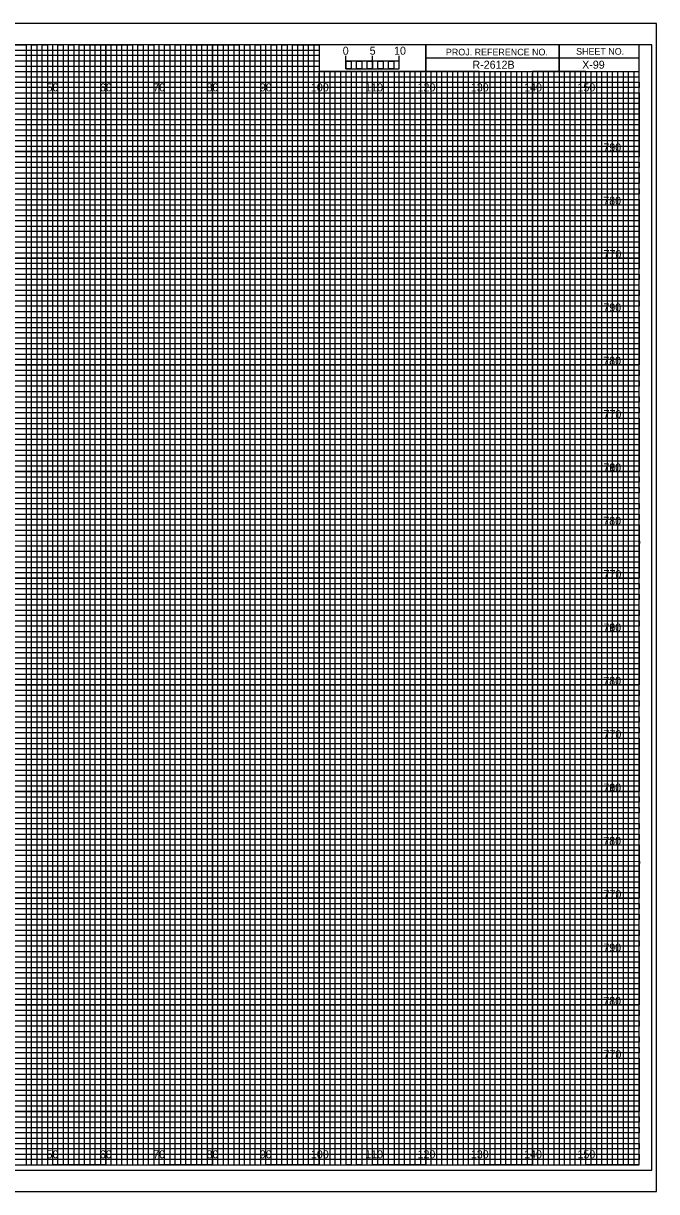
# Model space of a CAD drawing. Extents: x -13 to 323, y -5 to 214.
# Drawn here: x 204.5 to 323.3, y -5 to 214 of the extents above; entities that cross this region are included whole.
import ezdxf

# ---------------------------------------------------------------- set-up
doc = ezdxf.new("R2010")
doc.units = 0
for name, color, linetype in [('Prop XS Bar Scale Labels', 7, 'Continuous'), ('Prop XS Elevation Labels', 7, 'Continuous'), ('Prop XS Offset Labels', 7, 'Continuous'), ('Prop XS Project Number', 7, 'Continuous'), ('Prop XS Sheet Number', 7, 'Continuous'), ('Sheet Cross Section CELL', 7, 'Continuous'), ('Sheet Cross Section Grid Major CELL', 7, 'Continuous'), ('Sheet Cross Section Grid Middle CELL', 7, 'Continuous'), ('Sheet Cross Section Grid Minor 1 CELL', 7, 'Continuous'), ('Sheet Cross Section Grid Minor 2 CELL', 7, 'Continuous'), ('Sheet Cross Section Scale CELL', 7, 'Continuous'), ('Sheet Cutting Line CELL', 7, 'Continuous'), ('Sheet DOT Grid CELL', 7, 'Continuous'), ('Sheet Plot Border Inside CELL', 7, 'Continuous'), ('Sheet Plot Border Outside CELL', 7, 'Continuous')]:
    doc.layers.add(name, color=color, linetype=linetype)

msp = doc.modelspace()

# ---------------------------------------------------------------- linework, layer by layer
at = {"layer": 'Sheet Cross Section CELL'}
for p, q in [((305, 210), (305, 205)), ((305, 205), (305, 210)), ((280, 207.5), (280, 205)), ((320, 207.49), (280, 207.49)), ((280, 205), (320, 205))]:
    msp.add_line(p, q, dxfattribs=at)
for points in [[(320, 210), (0, 210), (0, 0), (320, 0)], [(280, 210), (260, 210), (260, 205.03), (280, 205.03)], [(320, 210), (280, 210), (280, 205), (320, 205)]]:
    msp.add_lwpolyline(points, close=True, dxfattribs=at)
at = {"layer": 'Sheet Cross Section Grid Major CELL'}
for p, q in [((210, 210), (200, 210)), ((210, 0), (210, 210)), ((230, 210), (220, 210)), ((220, 210), (220, 0)), ((230, 0), (230, 210)), ((250, 210), (240, 210)), ((240, 210), (240, 0)), ((250, 0), (250, 210)), ((260, 210), (260, 0)), ((270, 0), (270, 205)), ((290, 205), (280, 205)), ((280, 205), (280, 0)), ((290, 0), (290, 205)), ((310, 205), (300, 205)), ((300, 205), (300, 0)), ((310, 0), (310, 205)), ((220, 0), (210, 0)), ((240, 0), (230, 0)), ((260, 0), (250, 0)), ((280, 0), (270, 0)), ((300, 0), (290, 0)), ((320, 0), (310, 0)), ((320, 0), (320, 0))]:
    msp.add_line(p, q, dxfattribs=at)
for points in [[(0, 200), (320, 200), (320, 190), (0, 190)], [(0, 180), (320, 180), (320, 170), (0, 170)], [(0, 160), (320, 160), (320, 150), (0, 150)], [(0, 140), (320, 140), (320, 130), (0, 130)], [(0, 120), (320, 120), (320, 110), (0, 110)], [(0, 100), (320, 100), (320, 90), (0, 90)], [(0, 80), (320, 80), (320, 70), (0, 70)], [(0, 60), (320, 60), (320, 50), (0, 50)], [(0, 40), (320, 40), (320, 30), (0, 30)], [(0, 20), (320, 20), (320, 10), (0, 10)]]:
    msp.add_lwpolyline(points, dxfattribs=at)
at = {"layer": 'Sheet Cross Section Grid Middle CELL'}
for points in [[(195, 210), (205, 210), (205, 0), (215, 0), (215, 210), (225, 210), (225, 0), (235, 0), (235, 210), (245, 210), (245, 0), (255, 0), (255, 210), (259.93, 210), (260, 210), (260, 205), (264.99, 205), (264.99, 0), (275, 0), (275, 205), (285, 205), (285, 0), (295, 0), (295, 205), (305, 205), (305, 0), (315, 0), (315, 205)], [(0, 205), (275, 205)], [(0, 185), (320, 185), (320, 195), (0, 195)], [(0, 165), (320, 165), (320, 175), (0, 175)], [(0, 145), (320, 145), (320, 155), (0, 155)], [(0, 125), (320, 125), (320, 135), (0, 135)], [(0, 105), (320, 105), (320, 115), (0, 115)], [(0, 85), (320, 85), (320, 95), (0, 95)], [(0, 65), (320, 65), (320, 75), (0, 75)], [(0, 45), (320, 45), (320, 55), (0, 55)], [(0, 25), (320, 25), (320, 35), (0, 35)], [(0, 5), (320, 5), (320, 15), (0, 15)]]:
    msp.add_lwpolyline(points, dxfattribs=at)
at = {"layer": 'Sheet Cross Section Grid Minor 1 CELL'}
for p, q in [((0, 209), (260, 209)), ((260, 209), (260, 207.98)), ((260, 207.98), (0, 207.98)), ((0, 207), (260, 207)), ((260, 205.89), (0, 205.89)), ((260, 207), (260, 205.89)), ((0, 204), (320, 204))]:
    msp.add_line(p, q, dxfattribs=at)
for points in [[(0, 203), (270, 203), (320, 203), (320, 202), (0, 202)], [(0, 201), (320, 201), (320, 199), (0, 199)], [(0, 198), (320, 198), (320, 197), (0, 196.98)], [(0, 196), (320, 196), (320, 194), (0, 194)], [(0, 193), (320, 193), (320, 192), (0, 192)], [(0, 191), (320, 191), (320, 189), (0, 189)], [(0, 188), (320, 188), (320, 187), (0, 187)], [(0, 186), (320, 186), (320, 184), (0, 184)], [(0, 183), (320, 183), (320, 182), (0, 182)], [(0, 181), (320, 181), (320, 179), (0, 179)], [(0, 178), (320, 178), (320, 177), (0, 177)], [(0, 176), (320, 176), (320, 173.95), (320, 173), (320, 172), (0, 172)], [(0, 174), (320, 174), (320, 173), (0, 173)], [(0, 171), (320, 171), (320, 169), (0, 169.03)], [(0, 169.03), (320, 169), (320, 168), (0, 168)], [(0, 167), (320, 167), (320, 166), (0, 166)], [(0, 164), (320, 164), (320, 163), (0, 163)], [(0, 162), (320, 162), (320, 161), (0, 161)], [(-0.07, 158.89), (320, 158.89), (320, 157.88), (-0.07, 157.88)], [(0, 157), (320, 157), (320, 156), (0, 156)], [(0, 154), (320, 154), (320, 153), (0, 153)], [(0, 152), (320, 152), (320, 151), (0, 151)], [(0, 149), (320, 149), (320, 148), (0, 148)], [(0, 147), (320, 147), (320, 146), (0, 146)], [(0, 144), (320, 144), (320, 143), (0, 143)], [(0, 142), (320, 142), (320, 141), (0, 141)], [(0, 139), (320, 139), (319.99, 137.98), (0, 138)], [(0, 137), (320, 137), (320, 136), (0, 136)], [(0, 134), (320, 134), (320, 133), (0, 133)], [(0, 132), (320, 132), (320, 131), (0, 131)], [(0, 129), (320, 129), (320, 128), (0, 128)], [(0, 127), (320, 127), (320, 126), (0, 126)], [(0, 124), (320, 124), (320, 123), (0, 123)], [(0, 122), (320, 122), (320, 121), (0, 121)], [(0, 119), (320, 119), (320, 118), (0, 118)], [(0, 116.99), (320.07, 116.91), (320, 116), (0, 116)], [(0, 114), (320, 114), (320, 113), (0, 113)], [(0, 112), (320, 112), (320, 111), (0, 111)], [(0, 109), (320, 109), (320, 108), (0, 108)], [(0, 107), (320, 107), (320, 106), (0, 106)], [(0, 104), (320, 104), (320, 103), (0, 103)], [(0, 102), (320, 102), (320, 101), (0, 101)], [(0, 99), (320, 99), (320, 98), (0, 98)], [(0, 97), (320, 97), (320, 96), (0, 96)], [(0, 94), (320, 94), (320, 93), (0, 93)], [(0, 92), (320, 92), (320, 91), (0, 91)], [(0, 89), (320, 89), (320, 88), (0, 88)], [(0, 87), (320, 87), (320, 86), (0, 86)], [(0, 84), (320, 84), (320, 83), (0, 83)], [(0, 82), (320, 82), (320, 81), (0, 81)], [(0, 79), (320, 79), (319.99, 77.98), (0, 78)], [(0, 77), (320, 77), (320, 76), (0, 76)], [(0, 74), (320, 74), (320, 73), (0, 73)], [(0, 72), (320, 72), (320, 71), (0, 71)], [(0, 69), (320, 69), (320, 68), (0, 68)], [(0, 67), (320, 67), (320, 66), (0, 66)], [(0, 64), (320, 64), (320, 63), (0, 63)], [(0, 62), (320, 62), (320, 61), (0, 61)], [(0, 59), (320, 59), (320, 58), (0, 58)], [(0, 56.99), (320.07, 56.91), (320, 56), (0, 56)], [(0, 54), (320, 54), (320, 53), (0, 53)], [(0, 52), (320, 52), (320, 51), (0, 51)], [(0, 49), (320, 49), (320, 48), (0, 48)], [(0, 47), (320, 47), (320, 46), (0, 46)], [(0, 44), (320, 44), (320, 43), (0, 43)], [(0, 42), (320, 42), (320, 41), (0, 41)], [(0, 39), (320, 39), (320, 38), (0, 38)], [(0, 37), (320, 37), (320, 36), (0, 36)], [(0, 34), (320, 34), (320, 33), (0, 33)], [(0, 32), (320, 32), (320, 31), (0, 31)], [(0, 29), (320, 29), (320, 28), (0, 28)], [(0, 27), (320, 27), (320, 26), (0, 26)], [(0, 24), (320, 24), (320, 23), (0, 23)], [(0, 22), (320, 22), (320, 21), (0, 21)], [(0, 19), (320, 19), (320, 18), (0, 18)], [(0, 17), (320, 17), (320, 16), (0, 16)], [(0, 14), (320, 14), (320, 13), (0, 13)], [(0, 12), (320, 12), (320, 11), (0, 11)], [(0, 9), (320, 9), (320, 8), (0, 8)], [(0, 7), (320, 7), (320, 6), (0, 6)], [(0, 4), (320, 4), (320, 3), (0, 3)], [(0, 2), (320, 2), (320, 1), (0, 1)]]:
    msp.add_lwpolyline(points, dxfattribs=at)
at = {"layer": 'Sheet Cross Section Grid Minor 2 CELL'}
for p, q in [((267, 205), (266.01, 205)), ((266.01, 205), (266.01, 0)), ((267, 0), (267, 205)), ((269, 205), (268, 205)), ((268, 205), (268, 0)), ((269, 0), (269, 205)), ((266.01, 0), (265, 0)), ((268, 0), (267, 0))]:
    msp.add_line(p, q, dxfattribs=at)
for points in [[(205, 0), (206, 0), (206, 210), (207, 210), (207, 0)], [(207, 0), (208, 0), (208, 210), (209, 210), (209, 0)], [(210, 0), (211, 0), (211, 210), (212, 210), (212, 0)], [(212, 0), (213, 0), (213, 210), (214, 210), (214, 0)], [(215, 0), (216, 0), (216, 210), (217, 210), (217, 0)], [(217, 0), (218, 0), (218, 210), (219, 210), (219, 0)], [(220, 0), (221, 0), (221, 210), (222, 210), (222, 0)], [(222, 0), (223, 0), (223, 210), (224, 210), (224, 0)], [(225, 0), (226, 0), (226, 210), (227, 210), (227, 0)], [(227, 0), (228, 0), (228, 210), (229, 210), (229, 0)], [(230, 0), (231, 0), (231, 210), (232, 210), (232, 0)], [(232, 0), (233, 0), (233, 210), (234, 210), (234, 0)], [(235, 0), (236, 0), (236, 210), (237, 210), (237, 0)], [(237, 0), (238, 0), (238, 210), (239, 210), (239, 0)], [(240, 0), (241, 0), (241, 210), (242, 210), (242, 0)], [(242, 0), (243, 0), (243, 210), (244, 210), (244, 0)], [(245, 0), (246, 0), (246, 210), (247, 210), (247, 0)], [(247, 0), (248, 0), (248, 210), (249, 210), (249, 0)], [(250, 0), (251, 0), (251, 210), (252, 210), (252, 0)], [(252, 0), (253, 0), (253, 210), (254, 210), (254, 0)], [(255, 0), (256, 0), (256, 210), (257, 210), (257, 0)], [(257, 0), (258, 0), (258, 210), (259, 210), (259, 0)], [(260, 0), (261, 0), (261, 205), (262.02, 205), (262.02, 0)], [(262, 0), (263, 0), (263, 205), (263.99, 205), (263.99, 0)], [(270, 0), (270.98, 0), (270.98, 205), (272, 205), (272, 0)], [(272, 0), (273, 0), (273, 205), (274.05, 205), (274.05, 0)], [(275, 0), (276, 0), (276, 205), (277, 205), (277, 0)], [(277, 0), (278, 0), (278, 205), (279, 205), (279, 0)], [(280, 0), (281, 0), (281, 205), (282, 205), (282, 0)], [(282, 0), (283, 0), (283, 205), (284, 205), (284, 0)], [(285, 0), (286, 0), (286, 205), (287, 205), (287, 0)], [(287, 0), (288, 0), (288, 205), (289, 205), (289, 0)], [(290, 0), (291, 0), (291, 205), (292, 205), (292, 0)], [(292, 0), (293, 0), (293, 205), (294, 205), (294, 0)], [(295, 0), (296, 0), (296, 205), (297, 205), (297, 0)], [(297, 0), (298, 0), (298, 205), (299, 205), (299, 0)], [(300, 0), (301, 0), (301, 205), (302, 205), (302, 0)], [(302, 0), (303, 0), (303, 205), (304, 205), (304, 0)], [(305, 0), (306, 0), (306, 205), (307, 205), (307, 0)], [(307, 0), (308, 0), (308, 205), (309, 205), (309, 0)], [(310, 0), (311, 0), (311, 205), (312, 205), (312, 0)], [(312, 0), (313, 0), (313, 205), (314, 205), (314, 0)], [(315, 0), (316, 0), (316, 205), (317, 205), (317, 0)], [(317, 0), (318, 0), (318, 205), (319, 205), (319, 0)]]:
    msp.add_lwpolyline(points, dxfattribs=at)
at = {"layer": 'Sheet Cross Section Scale CELL'}
for p, q in [((265, 205.49), (265, 207.9)), ((265, 206.9), (265, 207.9)), ((270, 205.49), (270, 207.9)), ((275, 205.49), (275, 207.9)), ((275, 206.9), (275, 207.9))]:
    msp.add_line(p, q, dxfattribs=at)
for points in [[(275, 206.9), (265, 206.9), (265, 205.49), (275, 205.49)], [(265, 206.9), (266, 206.9), (266, 205.49), (265, 205.49)], [(267, 206.9), (268, 206.9), (268, 205.49), (267, 205.49)], [(269, 206.9), (270, 206.9), (270, 205.49), (269, 205.49)], [(271, 206.9), (272, 206.9), (272, 205.49), (271, 205.49)], [(273, 206.9), (274, 206.9), (274, 205.49), (273, 205.49)]]:
    msp.add_lwpolyline(points, close=True, dxfattribs=at)
at = {"layer": 'Sheet Cutting Line CELL'}
for p, q in [((323.3, 214), (-13.4, 214)), ((-13.4, -5), (323.3, -5))]:
    msp.add_line(p, q, dxfattribs=at)
at = {"layer": 'Sheet DOT Grid CELL'}
for p, q in [((210, 0), (210, 210)), ((220, 0), (220, 210)), ((230, 0), (230, 210)), ((240, 0), (240, 210)), ((250, 0), (250, 210)), ((260, 0), (260, 204.69)), ((270, 0), (270, 204.69)), ((280, 0), (280, 204.69)), ((290, 0), (290, 204.69)), ((300, 0), (300, 204.69)), ((310, 0), (310, 204.69)), ((0, 200), (320, 200)), ((0, 190), (320, 190)), ((0, 180), (320, 180)), ((0, 170), (320, 170)), ((0, 160), (320, 160)), ((0, 150), (320, 150)), ((0, 140), (320, 140)), ((0, 130), (320, 130)), ((0, 120), (320, 120)), ((0, 110), (320, 110)), ((0, 100), (320, 100)), ((0, 90), (320, 90)), ((0, 80), (320, 80)), ((0, 70), (320, 70)), ((0, 60), (320, 60)), ((0, 50), (320, 50)), ((0, 40), (320, 40)), ((0, 30), (320, 30)), ((0, 20), (320, 20)), ((0, 10), (320, 10))]:
    msp.add_line(p, q, dxfattribs=at)
at = {"layer": 'Sheet Plot Border Inside CELL'}
msp.add_lwpolyline([(-10.8, -1), (322.4, -1), (322.4, 210), (-10.8, 210)], close=True, dxfattribs=at)
at = {"layer": 'Sheet Plot Border Outside CELL'}
msp.add_lwpolyline([(-13.4, -5), (323.3, -5), (323.3, 214), (-13.4, 214)], close=True, dxfattribs=at)

# ---------------------------------------------------------------- texts
at = {"layer": 'Prop XS Bar Scale Labels'}
for s, p in [('5', (269.47, 208.12)), ('10', (274.04, 208.12))]:
    msp.add_text(s, height=1.5, dxfattribs=at).set_placement(p)
at = {"layer": 'Prop XS Elevation Labels'}
for s, p in [('790', (313.3, 190)), ('780', (313.28, 180)), ('770', (313.33, 170)), ('790', (313.3, 160)), ('780', (313.28, 150)), ('770', (313.33, 140)), ('790', (313.3, 130)), ('760', (313.3, 130)), ('780', (313.28, 120)), ('770', (313.33, 110)), ('790', (313.3, 100)), ('760', (313.3, 100)), ('780', (313.28, 90)), ('770', (313.33, 80)), ('790', (313.3, 70)), ('760', (313.3, 70)), ('780', (313.28, 60)), ('770', (313.33, 50)), ('790', (313.3, 40)), ('780', (313.28, 30)), ('770', (313.33, 20))]:
    msp.add_text(s, height=1.5, dxfattribs=at).set_placement(p)
at = {"layer": 'Prop XS Offset Labels'}
for s, p in [('50', (208.86, 201.25)), ('60', (218.86, 201.25)), ('70', (228.86, 201.25)), ('80', (238.86, 201.25)), ('90', (248.86, 201.25)), ('100', (258.44, 201.25)), ('110', (268.62, 201.25)), ('120', (278.44, 201.25)), ('130', (288.44, 201.25)), ('140', (298.44, 201.25)), ('150', (308.44, 201.25)), ('50', (208.86, 1.25)), ('60', (218.86, 1.25)), ('70', (228.86, 1.25)), ('80', (238.86, 1.25)), ('90', (248.86, 1.25)), ('100', (258.44, 1.25)), ('110', (268.62, 1.25)), ('120', (278.44, 1.25)), ('130', (288.44, 1.25)), ('140', (298.44, 1.25)), ('150', (308.44, 1.25))]:
    msp.add_text(s, height=1.5, dxfattribs=at).set_placement(p)
at = {"layer": 'Prop XS Project Number'}
msp.add_text('R-2612B', height=1.5, dxfattribs=at).set_placement((288.74, 205.5))
at = {"layer": 'Prop XS Sheet Number'}
msp.add_text('X-99', height=1.5, dxfattribs=at).set_placement((309.32, 205.5))
at = {"layer": 'Sheet Cross Section CELL'}
for s, p in [('PROJ. REFERENCE NO.', (283.77, 207.99)), ('SHEET NO.', (308.19, 208.12))]:
    msp.add_text(s, height=1.25, dxfattribs=at).set_placement(p)
at = {"layer": 'Sheet Cross Section Scale CELL'}
msp.add_text('0', height=1.5, dxfattribs=at).set_placement((264.41, 208.12))

doc.saveas('drawing.dxf')
